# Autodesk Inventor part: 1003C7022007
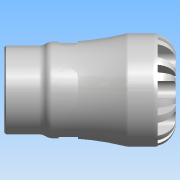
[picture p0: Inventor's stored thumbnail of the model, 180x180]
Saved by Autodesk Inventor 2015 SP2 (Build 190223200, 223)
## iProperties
Created: 2016-12
Part Number: 1003C7022007
Material: PVC-Piping
Description: PLASSON FEMALE COPPER ADAPTOR 22X3/4" SERIES 1
Document SubType Name: Modeling
Designer: KIM
Mass: 664.223 g
Surface Area: 733.008 cm^2
Volume: 474.445 cm^3
Density: 1.4 g/cm^3
Appearance: Smooth - White
Author: KIM
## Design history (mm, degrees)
derived "1003C.ipt"
feature "Solid1::1003C.ipt"
tag "TaggingFeature1"
body "Solid1"
other parameters: "d0" = 71, "d1" = 20.16, "d2" = 22, "d3" = 28.2, "d4" = 47, "d6" = 48, "d8" = 39.95, "d13" = 7.52, "d14" = 7.52, "d15" = 0, "d17" = 360 deg, "d19" = 8 deg, "d20" = 0.44, "d21" = 0.44, "d22" = 8 deg, "d24" = 0, "d26" = 360 deg, "d32" = 4.7, "d33" = 4.7, "d39" = 0.72351, "d42" = 24.117, "d43" = 36.66, "d46" = 1.83333, "d47" = 18, "d48" = 22.91115, "d50" = 1.65, "d51" = 0.47, "d54" = 7.99, "d55" = 5.17, "d57" = 15.288, "d58" = 0, "d68" = 360 deg, "d72" = 0.44, "d74" = 0, "d76" = 6.7915, "d_" = 22, "E_" = 47, "H_" = 71, "l_" = 48, "Rp" = 24.117, "l_2" = 18, "d9" = 9.4, "d11" = 47, "d12" = 28.2, "d49" = 5
